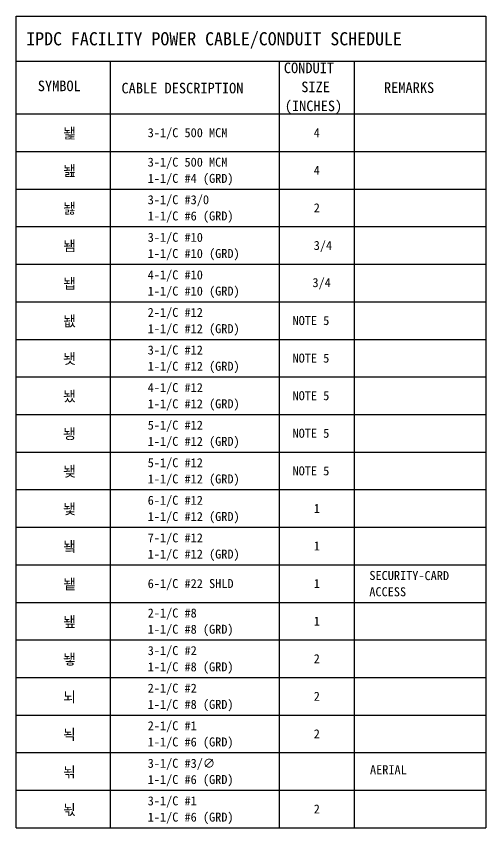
# Model space of a CAD drawing. Extents: x 0 to 0.521, y 0 to 0.9.
import ezdxf

# ---------------------------------------------------------------- set-up
doc = ezdxf.new("R2010")
doc.units = 0
for name, color, linetype in [('HS_Dimensions_and_Text', 7, 'Continuous'), ('HS_Table Lines', 7, 'Continuous'), ('HS_Table_Border', 7, 'Continuous'), ('HS_Table_Lines', 7, 'Continuous')]:
    doc.layers.add(name, color=color, linetype=linetype)

msp = doc.modelspace()

# ---------------------------------------------------------------- linework, layer by layer
at = {"layer": 'HS_Table Lines'}
msp.add_line((0, 0.79167), (0.52083, 0.79167), dxfattribs=at)
at = {"layer": 'HS_Table_Border'}
for p, q in [((0, 0), (0, 0.9)), ((0, 0.9), (0.52083, 0.9)), ((0.52083, 0.9), (0.52083, 0)), ((0, 0.85), (0.52083, 0.85)), ((0, 0), (0.52083, 0)), ((0, 0), (0.52083, 0))]:
    msp.add_line(p, q, dxfattribs=at)
at = {"layer": 'HS_Table_Lines'}
for p, q in [((0.10417, 0.85), (0.10417, 0)), ((0.29167, 0.85), (0.29167, 0)), ((0.375, 0.85), (0.375, 0)), ((0, 0.75), (0.52083, 0.75)), ((0, 0.70833), (0.52083, 0.70833)), ((0, 0.66667), (0.52083, 0.66667)), ((0, 0.625), (0.52083, 0.625)), ((0, 0.58333), (0.52083, 0.58333)), ((0, 0.54167), (0.52083, 0.54167)), ((0, 0.5), (0.52083, 0.5)), ((0, 0.45833), (0.52083, 0.45833)), ((0, 0.41667), (0.52083, 0.41667)), ((0, 0.375), (0.52083, 0.375)), ((0, 0.33333), (0.52083, 0.33333)), ((0, 0.29167), (0.52083, 0.29167)), ((0, 0.25), (0.52083, 0.25)), ((0, 0.20833), (0.52083, 0.20833)), ((0, 0.16667), (0.52083, 0.16667)), ((0, 0.125), (0.52083, 0.125)), ((0, 0.125), (0.52083, 0.125)), ((0, 0.08333), (0.52083, 0.08333)), ((0, 0.04167), (0.52083, 0.04167))]:
    msp.add_line(p, q, dxfattribs=at)

# ---------------------------------------------------------------- texts
at = {"layer": 'HS_Dimensions_and_Text'}
for s, height, rotation, p in [('IPDC FACILITY POWER CABLE/CONDUIT SCHEDULE', 0.0145833, 360, (0.0111, 0.86771)), ('CONDUIT ', 0.0117, 360, (0.29684, 0.83684)), ('SYMBOL', 0.0117, 360, (0.02391, 0.81688)), ('CABLE DESCRIPTION', 0.0117, 360, (0.11672, 0.81447)), ('SIZE ', 0.0117, 360, (0.31618, 0.81578)), ('REMARKS', 0.0117, 360, (0.40792, 0.81498)), ('(INCHES)', 0.0117, 360, (0.29788, 0.79472)), ('놽', 0.01167, 360, (0.05208, 0.76448)), ('3-1/C 500 MCM', 0.01, 360, (0.14583, 0.76583)), ('4', 0.01, 360, (0.33, 0.76583)), ('3-1/C 500 MCM', 0.01, 360, (0.14583, 0.73317)), ('놾', 0.01167, 360, (0.05208, 0.72281)), ('4', 0.01, 360, (0.33, 0.72417)), ('1-1/C #4 (GRD)', 0.01, 360, (0.14583, 0.71517)), ('3-1/C #3/0', 0.01, 360, (0.14583, 0.6915)), ('놿', 0.01167, 360, (0.05208, 0.68114)), ('1-1/C #6 (GRD)', 0.01, 360, (0.14583, 0.6735)), ('2 ', 0.01, 360, (0.33, 0.6825)), ('3-1/C #10', 0.01, 360, (0.14583, 0.64983)), ('뇀', 0.01167, 360, (0.05208, 0.63946)), ('3/4', 0.01, 360, (0.33, 0.64083)), ('1-1/C #10 (GRD)', 0.01, 360, (0.14583, 0.63183)), ('4-1/C #10', 0.01, 360, (0.14583, 0.60817)), ('뇁', 0.01167, 360, (0.05208, 0.59779)), ('3/4', 0.01, 360, (0.32859, 0.59961)), ('1-1/C #10 (GRD)', 0.01, 360, (0.14583, 0.59017)), ('2-1/C #12', 0.01, 360, (0.14583, 0.5665)), ('뇂', 0.01167, 360, (0.05208, 0.55612)), ('NOTE 5', 0.01, 360, (0.3065, 0.5575)), ('1-1/C #12 (GRD)', 0.01, 360, (0.14583, 0.5485)), ('3-1/C #12', 0.01, 360, (0.14583, 0.52483)), ('뇃', 0.01167, 360, (0.05208, 0.51444)), ('NOTE 5', 0.01, 360, (0.3065, 0.51583)), ('1-1/C #12 (GRD)', 0.01, 360, (0.14583, 0.50683)), ('4-1/C #12', 0.01, 360, (0.14583, 0.48317)), ('뇄', 0.01167, 360, (0.05208, 0.47277)), ('NOTE 5', 0.01, 360, (0.3065, 0.47417)), ('1-1/C #12 (GRD)', 0.01, 360, (0.14583, 0.46517)), ('5-1/C #12', 0.01, 360, (0.14583, 0.4415)), ('뇅', 0.01167, 360, (0.05208, 0.4311)), ('NOTE 5', 0.01, 360, (0.3065, 0.4325)), ('1-1/C #12 (GRD)', 0.01, 360, (0.14583, 0.4235)), ('5-1/C #12', 0.01, 360, (0.14583, 0.39983)), ('뇆', 0.01167, 360, (0.05208, 0.38942)), ('NOTE 5', 0.01, 360, (0.3065, 0.39083)), ('1-1/C #12 (GRD)', 0.01, 360, (0.14583, 0.38183)), ('뇇', 0.01167, 360, (0.05208, 0.34775)), ('6-1/C #12', 0.01, 360, (0.14583, 0.35817)), ('1-1/C #12 (GRD)', 0.01, 360, (0.14583, 0.34017)), ('1', 0.01, 360, (0.33, 0.34917)), ('7-1/C #12', 0.01, 360, (0.14583, 0.3165)), ('뇈', 0.01167, 360, (0.05208, 0.30608)), ('1', 0.01, 360, (0.33, 0.3075)), ('1-1/C #12 (GRD)', 0.01, 360, (0.14583, 0.2985)), ('SECURITY-CARD ', 0.01, 359.84, (0.39168, 0.27483)), ('뇉', 0.01167, 360, (0.05208, 0.2644)), ('6-1/C #22 SHLD', 0.01, 360, (0.14583, 0.26583)), ('1', 0.01, 360, (0.33, 0.26583)), ('ACCESS', 0.01, 359.84, (0.39163, 0.25683)), ('2-1/C #8', 0.01, 360, (0.14583, 0.23317)), ('뇊', 0.01167, 360, (0.05208, 0.22273)), ('1-1/C #8 (GRD)', 0.01, 360, (0.14583, 0.21517)), ('1', 0.01, 360, (0.33, 0.22417)), ('3-1/C #2', 0.01, 360, (0.14583, 0.1915)), ('뇋', 0.01167, 360, (0.05208, 0.18106)), ('2', 0.01, 360, (0.33, 0.1825)), ('1-1/C #8 (GRD)', 0.01, 360, (0.14583, 0.1735)), ('2-1/C #2', 0.01, 360, (0.14583, 0.14983)), ('뇌', 0.01167, 360, (0.05208, 0.13938)), ('2', 0.01, 360, (0.33, 0.14083)), ('1-1/C #8 (GRD)', 0.01, 360, (0.14583, 0.13183)), ('2-1/C #1', 0.01, 360, (0.14583, 0.10817)), ('뇍', 0.01167, 360, (0.05208, 0.09771)), ('2', 0.01, 360, (0.33, 0.09917)), ('1-1/C #6 (GRD)', 0.01, 360, (0.14583, 0.09017)), ('3-1/C #3/∅', 0.01, 360, (0.14583, 0.0665)), ('뇎', 0.01167, 360, (0.05208, 0.05604)), ('AERIAL', 0.01, 360, (0.3924, 0.05942)), ('1-1/C #6 (GRD)', 0.01, 360, (0.14583, 0.0485)), ('뇏', 0.01167, 360, (0.05208, 0.01436)), ('3-1/C #1', 0.01, 360, (0.14583, 0.02483)), ('2', 0.01, 360, (0.33, 0.01583)), ('1-1/C #6 (GRD)', 0.01, 360, (0.14583, 0.00683))]:
    msp.add_text(s, height=height, rotation=rotation, dxfattribs=at).set_placement(p)

doc.saveas('drawing.dxf')
